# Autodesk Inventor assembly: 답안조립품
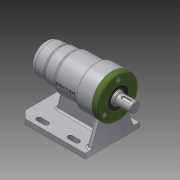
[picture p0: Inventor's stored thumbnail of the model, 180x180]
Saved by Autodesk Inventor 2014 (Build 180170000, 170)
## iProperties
Created: 2017-09
Part Number: 답안조립품
Document SubType Name: Assembly
Designer: user
Author: user
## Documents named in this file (9)
- C:\Users\user\Desktop\470907V1001\답안조립품.iam
- C:\Users\user\Desktop\470907V1001\본체.ipt
- C:\Users\user\Desktop\470907V1001\커버.ipt
- C:\Users\user\Desktop\470907V1001\볼트 M4 x 12.ipt
- C:\Users\user\Desktop\470907V1001\베어링 6004.ipt
- C:\Users\user\Desktop\470907V1001\축.ipt
- C:\Users\user\Desktop\470907V1001\오일 실 20x35x7.ipt
- C:\Users\user\Desktop\470907V1001\어댑터슬리브.ipt
- C:\Users\user\Desktop\470907V1001\베어링 51202.ipt
